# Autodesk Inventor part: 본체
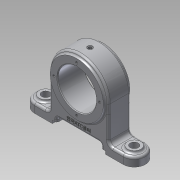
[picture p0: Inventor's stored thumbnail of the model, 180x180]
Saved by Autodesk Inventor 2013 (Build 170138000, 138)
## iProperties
Created: 2019-05
Part Number: 본체
Material: 알루미늄 6061
Document SubType Name: Modeling
Designer: Administrator
Density: 2.71 g/cm^3
Mass: 456.188 g
Surface Area: 323.072 cm^2
Volume: 168.335 cm^3
Author: Administrator
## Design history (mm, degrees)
sketch "스케치1"
  geometry: L1 (-40, 0)-(40, 0); L2 (40, 0)-(40, -48); L3 (40, -48)-(75, -48); L4 (75, -48)-(75, -60); L5 (75, -60)-(36, -60); L6 (36, -60)-(36, -56); L7 (36, -56)-(30, -56); L8 (30, -56)-(30, -50); L9 (30, -50)-(-30, -50); L10 (-30, -50)-(-30, -56); L11 (-30, -56)-(-36, -56); L12 (-36, -56)-(-36, -60); L13 (-36, -60)-(-75, -60); L14 (-75, -60)-(-75, -48); L15 (-75, -48)-(-40, -48); L16 (-40, -48)-(-40, 0); A1 r 40 centre (0, 0) between (40, 0) and (-40, 0); 3 further points
  constraints: 32 end point, 11 parallel, 3 perpendicular, 2 coincident, 2 midpoint, 2 point on circle, 1 centre point, 1 collinear, 1 horizontal, 1 horizontal alignment, 1 tangent, 1 vertical alignment
  dimensions: "d5" = 4 distance of L11.end L12.end; "d6" = 4 distance of L5.end L6.end; "d7" = 60 distance between parallel lines of L8 L10; "d8" = 150 distance between parallel lines of L4 L14; "d9" = 60 distance between parallel lines of L13 L1; "d11" = 10 distance between parallel lines of L13 L9; "d12" = 75 distance from line of point (0, 0) L14; "d13" = 12 distance of L13.end L14.end; "d14" = 12 distance of L3.end L4.end; "d15" = 72 distance between parallel lines of L6 L12; "d16" = 80 diameter of A1; "d17" = 39 distance between parallel lines of L12 L14
extrude "돌출1" new body sketch "스케치1" stored distance "d18" = 30; taper "d19" = 0 deg
sketch "스케치3"
  geometry: C1 r 36 at (0, 0); 1 further point
  constraints: 1 centre point, 1 coincident
  dimensions: "d21" = 72 diameter of C1
extrude "돌출2" join sketch "스케치3" stored distance "d22" = 36; taper "d23" = 0 deg
sketch "스케치5"
  geometry: C1 r 36 at (0, 0) reference; C2 r 26 at (0, 0)
  constraints: 1 centre point, 1 coincident
  dimensions: "d24" = 52 diameter of C2
extrude "돌출3" cut sketch "스케치5" stored distance "d25" = 36; taper "d26" = 0 deg
sketch "스케치6"
  geometry: C1 r 9 at (20, 15); 1 further point
  constraints: 1 centre point, 1 horizontal alignment
  dimensions: "d27" = 18 diameter of C1; "d29" = 60 distance of point (-40, 15) C1.centre
extrude "돌출4" join sketch "스케치6" distance "d30" = 3; taper "d31" = 0 deg
sketch "스케치7"
  geometry: C1 r 9 at (0, 0) reference; C2 r 5.5 at (0, 0); 1 further point
  constraints: 1 centre point, 1 coincident
  dimensions: "d32" = 11 diameter of C2
extrude "돌출5" cut sketch "스케치7" stored distance "d33" = 3; taper "d34" = 0 deg
sketch "스케치8" dims "d35" = 62
  geometry: C1 r 26 at (0, 0) reference; C2 r 36 at (0, 0) reference; 2 further points
  constraints: 2 vertical alignment, 1 coincident, 2 other
hole "구멍1" sketch "스케치8" at (0, 31) diameter "d36" = 3.242; stored, may be unused: countersink angle "d40" = 90 deg, drill point angle "d42" = 118 deg; dims "d37" = 6, "d38" = 4, "d39" = 2, "d41" = 8
sketch "스케치9"
  geometry: C1 r 1.5 at (0, 26); 1 further point
  constraints: 2 vertical alignment, 1 centre point, 1 other
  dimensions: "d46" = 3 diameter of C1
extrude "돌출6" cut sketch "스케치9" stored distance "d47" = 3; taper "d48" = 0 deg
node "작업 평면1"
sketch "스케치10"
  geometry: 2 further points
  constraints: 1 coincident
hole "구멍2" sketch "스케치10" at (0, 0) diameter "d49" = 4.917; stored, may be unused: countersink angle "d53" = 90 deg, drill point angle "d55" = 118 deg; dims "d50" = 8, "d51" = 7, "d52" = 1, "d54" = 10
sketch "스케치11"
  geometry: C1 r 1 at (0, 0); 1 further point
  constraints: 1 centre point, 1 coincident
  dimensions: "d56" = 2 diameter of C1
extrude "돌출7" cut sketch "스케치11" distance "d57" = 15.5; taper "d58" = 0 deg
fillet "모깎기1" dims "d59" = 3
fillet "모깎기2" dims "d60" = 15
fillet "모깎기3" dims "d61" = 3
fillet "모깎기4" dims "d62" = 6
fillet "모깎기5" dims "d63" = 3
fillet "모깎기6" dims "d64" = 3
fillet "모깎기7" dims "d65" = 3
node "작업 평면2"
sketch "스케치12"
  geometry: L1 (-27, -50)-(27, -50) reference; 2 further points
  constraints: 1 vertical alignment, 1 other
  dimensions: "d67" = 7 distance from line of L1 point (0, -43)
feature "엠보싱1" sketch "스케치12" dims "d5" = 4, "d6" = 4, "d7" = 60, "d8" = 150, "d9" = 60, "d11" = 10, "d12" = 75, "d13" = 12, "d14" = 12, "d15" = 72, "d16" = 80, "d17" = 39, "d68" = 0.5, "d69" = 0
chamfer "모따기1" distance "d70" = 1; stored, may be unused: second distance "d71" = 2, angle "d72" = 45 deg
node "솔리드1"
mirror "대칭2"
pattern_circular "원형 패턴1" dims angle "d44" = 360 deg
mirror "대칭3"
